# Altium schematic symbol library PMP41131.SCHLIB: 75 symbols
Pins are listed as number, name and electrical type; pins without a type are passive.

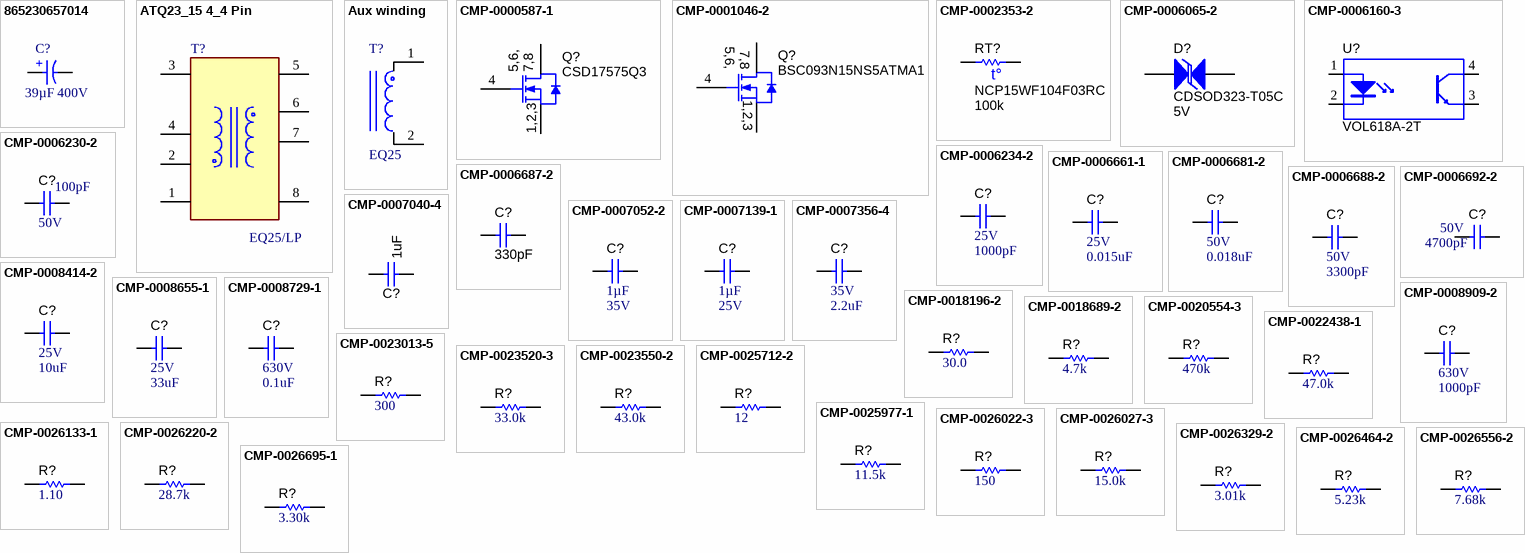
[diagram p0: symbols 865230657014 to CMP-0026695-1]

## 865230657014
designator C?  Rated Voltage (DC): 400V  Cap_F: 39µF
Aluminum Electrolytic Capacitor, Radial, THT, D10 x H20-mm, 39µF, 400V; Manufacturer: Yongming; PartNumber: KCXE2502G470MF; Capacitance Tolerance: +0%/-40%; Case/Size Code: D10 x H20mm; Dissipation Factor: 15%; Endurance: 2000h; Leakage Current: 264uA; Match Code: WCAP-ATG5; Ripple Current: 200mA; Technical Reference: ATJE1602203400DSPA7B0LR; Value: 39uF
footprint 400V27uF_Laydown
pins: 1 P, 2 N

## ATQ23_15 4_4 Pin
designator T?, comment EQ25/LP
ATQ23_15 4_4 Pin
footprint ATQ23.9_13.8_Remove Flywire
pins: 1, 2, 3, 4, 5, 6, 7, 8

## Aux winding
designator T?, comment EQ25
footprint ATQ23.7_15 4+4 Pin
pins: 1, 2

## CMP-0000587-1
designator Q?, comment CSD17575Q3
MOSFET, N-CH, 30 V, 60 A, DQG0008A (VSON-CLIP-8); Manufacturer: Texas Instruments; Alternate Manufacturer: None; U/M: EA; ChType: N; Value: 30V; Value1: 0.003; Rdson45_ohm: 3.2m; Value2: 23 nC; QgTyp_nC: 23; Vgs_V: 20V; IdsMax_A: 60A; AEC Category: Q101; SizeZ_mm: 1.1; SizeX_mm: 3.3; SizeArea_mm2: 10.89; SizeAreaWB_mm2: 18.49
footprint DQG0008A (SMD, 8-Leads, Body 3.3x3.3mm, Pitch 0.65mm)
footprint DQG0008A_NV (SMD, 8-Leads, Body 3.3x3.3mm, Pitch 0.65mm)
pins: 1 S, 2 S, 3 S, 4 G, 5 D, 6 D, 7 D, 8 D, 9 D

## CMP-0001046-2
designator Q?, comment BSC093N15NS5ATMA1
MOSFET, N-CH, 150 V, 87 A, PG-TDSON-8; Alternate Manufacturer: None; Manufacturer: Infineon Technologies; SizeZ_mm: 1.12; ChType: N; Value2: 33 nC; VdsMax_V: 150V; SizeX_mm: 5.99; SizeY_mm: 4.9; Vgs_V: 20V; QgTyp_nC: 33; Value: 150V; SizeArea_mm2: 29.351; AEC Category: Q101; IdsMax_A: 87A; SizeAreaWB_mm2: 55.131; U/M: EA
footprint PG-TDSON-8 (Infineon recommended land pattern)
pins: 1 S, 2 S, 3 S, 4 G, 5 D, 6 D, 7 D, 8 D, 9 D

## CMP-0002353-2
designator RT?, comment NCP15WF104F03RC  value 100k
Thermistor NTC, 100k ohm, 1%, 0402; Manufacturer: MuRata; TaMax_C: 125°C; SizeX_mm: 1; SizeY_mm: 0.5; TaMin_C: -40°C; Power_W: 100mW; SizeZ_mm: 0.6; SizeAreaWB_mm2: 3; U/M: EA
footprint 0402S (Based on C0402S footprint from PADS legacy)
footprint 0402 (0402 from SM-752 data)
footprint 0402L (0402 from SM-752 data)
footprint 0402M (0402 from SM-752 data)
pins: 1, 2

## CMP-0006065-2
designator D?, comment CDSOD323-T05C  value 5V
Diode, TVS, Bi, 5 V, SOD323, 2-Leads, Body 1.9x1.45mm, No Polarity Mark; Manufacturer: Bourns; Ppk: 350W; AEC Category: Q101
footprint SOD-323-Bi (SOD323, 2-Leads, Body 1.9x1.45mm, No Polarity Mark)
pins: 1, 2

## CMP-0006160-3
designator U?, comment VOL618A-2T
Optocoupler, 5 kV, 63-125% CTR, SMT; Manufacturer: Vishay-Semiconductor; Manufacturer: Vishay / Semiconductors; CTR (Max): 125%; SizeAreaWB_mm2: 74.42; CTR (Min): 63%; SizeZ_mm: 2.3; SizeX_mm: 10.2; SizeY_mm: 4.1; SizeArea_mm2: 41.82; Voltage_Isolation_Vrms: 5kV
footprint SOP254P1020X230-4 (VISHAY)
pins: 1 A, 2 K, 3 E, 4 C
1 alternate drawing of the same symbol

## CMP-0006230-2
designator C?, comment VDC_V: 50V  ValueDisplayed: 100pF  (hidden comment: 885012205055)
CAP, CERM, 100 pF, 50 V, +/- 10%, X7R, 0402; Manufacturer: Wurth Elektronik; TaMin_C: -55°C; Polarized: N; SizeAreaWB_mm2: 3; Value1: Unknown; U/M: EA; Value: 100pF; TaMax_C: 125°C; SizeZ_mm: 0.6; SizeX_mm: 1; SizeY_mm: 0.5; Cap_Case: 0402; CompType: Capacitor; AEC Category: Q200
footprint 0402 (0402 from SM-752 data)
footprint 0402S (Based on C0402S footprint from PADS legacy)
footprint 0402L (0402 from SM-752 data)
footprint 0402M (0402 from SM-752 data)
pins: 1, 2

## CMP-0006234-2
designator C?, comment VDC_V: 25V  ValueDisplayed: 1000pF  (hidden comment: C0402C102J3RACTU)
CAP, CERM, 1000 pF, 25 V, +/- 5%, X7R, 0402; Manufacturer: Kemet; TaMin_C: -55°C; Polarized: N; SizeAreaWB_mm2: 3; Value1: Unknown; U/M: EA; Value: 1000pF; TaMax_C: 125°C; SizeZ_mm: 0.6; SizeX_mm: 1; SizeY_mm: 0.5; Cap_Case: 0402; CompType: Capacitor; Cap_F: 1nF; AEC Category: Q200
footprint 0402 (0402 from SM-752 data)
footprint 0402S (Based on C0402S footprint from PADS legacy)
footprint 0402L (0402 from SM-752 data)
footprint 0402M (0402 from SM-752 data)
pins: 1, 2

## CMP-0006661-1
designator C?, comment VDC_V: 25V  ValueDisplayed: 0.015uF  (hidden comment: GRM155R71E153KA61D)
CAP, CERM, 0.015 uF, 25 V, +/- 10%, X7R, 0402; Manufacturer: MuRata; TaMin_C: -55°C; Polarized: N; SizeAreaWB_mm2: 3; Value1: Unknown; U/M: EA; TaMax_C: 125°C; SizeZ_mm: 0.6; SizeX_mm: 1; SizeY_mm: 0.5; Cap_Case: 0402; CompType: Capacitor; Cap_F: 15nF; AEC Category: Q200
footprint 0402 (0402 from SM-752 data)
footprint 0402S (Based on C0402S footprint from PADS legacy)
footprint 0402L (0402 from SM-752 data)
footprint 0402M (0402 from SM-752 data)
pins: 1, 2

## CMP-0006681-2
designator C?, comment VDC_V: 50V  ValueDisplayed: 0.018uF  (hidden comment: GRM155R71H183KA12D)
CAP, CERM, 0.018 uF, 50 V, +/- 10%, X7R, 0402; Manufacturer: MuRata; TaMin_C: -55°C; Polarized: N; SizeAreaWB_mm2: 3; Value1: Unknown; U/M: EA; TaMax_C: 125°C; SizeZ_mm: 0.6; SizeX_mm: 1; SizeY_mm: 0.5; Cap_Case: 0402; CompType: Capacitor; Cap_F: 18nF; AEC Category: Q200
footprint 0402 (0402 from SM-752 data)
footprint 0402S (Based on C0402S footprint from PADS legacy)
footprint 0402L (0402 from SM-752 data)
footprint 0402M (0402 from SM-752 data)
pins: 1, 2

## CMP-0006687-2
designator C?, comment ValueDisplayed: 330pF  (hidden comment: GRM155R71H331KA01D)
CAP, CERM, 330 pF, 50 V, +/- 10%, X7R, 0402; Manufacturer: MuRata; TaMin_C: -55°C; Polarized: N; SizeAreaWB_mm2: 3; Value1: Unknown; U/M: EA; Value: 330pF; TaMax_C: 125°C; SizeZ_mm: 0.6; SizeX_mm: 1; SizeY_mm: 0.5; Cap_Case: 0402; Value2: 50V; CompType: Capacitor; AEC Category: Q200
footprint 0402 (0402 from SM-752 data)
footprint 0402S (Based on C0402S footprint from PADS legacy)
footprint 0402L (0402 from SM-752 data)
footprint 0402M (0402 from SM-752 data)
pins: 1, 2

## CMP-0006688-2
designator C?, comment VDC_V: 50V  ValueDisplayed: 3300pF  (hidden comment: GRM155R71H332KA01D)
CAP, CERM, 3300 pF, 50 V, +/- 10%, X7R, 0402; Manufacturer: MuRata; TaMin_C: -55°C; Polarized: N; SizeAreaWB_mm2: 3; Value1: Unknown; U/M: EA; Value: 3300pF; TaMax_C: 125°C; SizeZ_mm: 0.6; SizeX_mm: 1; SizeY_mm: 0.5; Cap_Case: 0402; CompType: Capacitor; Cap_F: 3.3nF; AEC Category: Q200
footprint 0402 (0402 from SM-752 data)
footprint 0402S (Based on C0402S footprint from PADS legacy)
footprint 0402L (0402 from SM-752 data)
footprint 0402M (0402 from SM-752 data)
pins: 1, 2

## CMP-0006692-2
designator C?, comment VDC_V: 50V  ValueDisplayed: 4700pF  (hidden comment: GRM155R71H472KA01D)
CAP, CERM, 4700 pF, 50 V, +/- 10%, X7R, 0402; Manufacturer: MuRata; TaMin_C: -55°C; Polarized: N; SizeAreaWB_mm2: 3; Value1: Unknown; U/M: EA; Value: 4700pF; TaMax_C: 125°C; SizeZ_mm: 0.6; SizeX_mm: 1; SizeY_mm: 0.5; Cap_Case: 0402; CompType: Capacitor; Cap_F: 4.7nF; AEC Category: Q200
footprint 0402 (0402 from SM-752 data)
footprint 0402S (Based on C0402S footprint from PADS legacy)
footprint 0402L (0402 from SM-752 data)
footprint 0402M (0402 from SM-752 data)
pins: 1, 2

## CMP-0007040-4
designator C?, comment ValueDisplayed: 1uF  (hidden comment: C1608X7R1E105K080AB)
CAP, CERM, 1 µF, 25 V, +/- 10%, X7R, 0603; Manufacturer: TDK; Polarized: N; CompType: Capacitor; Value: 1uF; U/M: EA; Cap_F: 1µF; Value1: Unknown; VDC_V: 25V; TaMin_C: -55°C; TaMax_C: 125°C; Cap_Case: 0603; AEC Category: Q200; SizeArea_mm2: 1.28; SizeAreaWB_mm2: 4.68; SizeX_mm: 1.6; SizeY_mm: 0.8; SizeZ_mm: 1
footprint 0603 (0603 from SM-752 data)
footprint 0603_HV (Ernesto recommended land pattern.  26 mil between pads.)
footprint 0603L (0603 from SM-752 data)
footprint 0603S
footprint 0603M (0603 from SM-752 data)
pins: 1, 2

## CMP-0007052-2
designator C?, comment Cap_F: 1µF  VDC_V: 35V  (hidden comment: C1608X7R1V105K080AC)
CAP, CERM, 1 uF, 35 V, +/- 10%, X7R, 0603; Manufacturer: TDK; TaMin_C: -55°C; Polarized: N; SizeAreaWB_mm2: 4.68; Value1: Unknown; U/M: EA; Value: 1uF; TaMax_C: 125°C; SizeZ_mm: 1; SizeX_mm: 1.6; SizeY_mm: 0.8; Cap_Case: 0603; SizeArea_mm2: 1.28; CompType: Capacitor; AEC Category: Q200
footprint 0603 (0603 from SM-752 data)
footprint 0603_HV (Ernesto recommended land pattern.  26 mil between pads.)
footprint 0603L (0603 from SM-752 data)
footprint 0603S
footprint 0603M (0603 from SM-752 data)
pins: 1, 2

## CMP-0007139-1
designator C?, comment Cap_F: 1µF  VDC_V: 25V  (hidden comment: GCM188R71E105KA64D)
CAP, CERM, 1 uF, 25 V, +/- 10%, X7R, AEC-Q200 Grade 1, 0603; Manufacturer: MuRata; TaMin_C: -55°C; Polarized: N; SizeAreaWB_mm2: 4.68; Value1: Unknown; U/M: EA; Value: 1uF; TaMax_C: 125°C; SizeZ_mm: 1; SizeX_mm: 1.6; SizeY_mm: 0.8; Cap_Case: 0603; SizeArea_mm2: 1.28; CompType: Capacitor; AEC Qualified: Y; AEC Category: Q200
footprint 0603 (0603 from SM-752 data)
footprint 0603_HV (Ernesto recommended land pattern.  26 mil between pads.)
footprint 0603L (0603 from SM-752 data)
footprint 0603S
footprint 0603M (0603 from SM-752 data)
pins: 1, 2

## CMP-0007356-4
designator C?, comment VDC_V: 35V  ValueDisplayed: 2.2uF  (hidden comment: GRM188R6YA225KA12D)
CAP, CERM, 2.2 uF, 35 V, +/- 10%, X5R, 0603; Manufacturer: MuRata; TaMin_C: -55°C; Polarized: N; SizeAreaWB_mm2: 4.68; Value1: Unknown; U/M: EA; Value: 2.2uF; TaMax_C: 85°C; SizeZ_mm: 1; SizeX_mm: 1.6; SizeY_mm: 0.8; Cap_Case: 0603; SizeArea_mm2: 1.28; CompType: Capacitor; Cap_F: 2.2µF; AEC Category: Q200
footprint 0603 (0603 from SM-752 data)
footprint 0603_HV (Ernesto recommended land pattern.  26 mil between pads.)
footprint 0603L (0603 from SM-752 data)
footprint 0603S
footprint 0603M (0603 from SM-752 data)
pins: 1, 2

## CMP-0008414-2
designator C?, comment VDC_V: 25V  ValueDisplayed: 10uF  (hidden comment: TMK212BBJ106KG-T)
CAP, CERM, 10 uF, 25 V, +/- 10%, X5R, 0805; Manufacturer: Taiyo Yuden; TaMin_C: -55°C; Polarized: N; SizeAreaWB_mm2: 6.75; Value1: Unknown; U/M: EA; Value: 10uF; TaMax_C: 85°C; SizeZ_mm: 1.45; SizeX_mm: 2; SizeY_mm: 1.25; Cap_Case: 0805; SizeArea_mm2: 2.5; CompType: Capacitor; Cap_F: 10µF; AEC Category: Q200
footprint 0805_HV (0805 with 30mil clearance between pads)
footprint 0805M (0805 from SM-752 data)
footprint 0805 (0805 from SM-752 data)
footprint 0805L (0805 from SM-752 data)
footprint 0805_HV1 (Custom footprint based on analyzing multiple manufacturer recommendations)
pins: 1, 2

## CMP-0008655-1
designator C?, comment VDC_V: 25V  ValueDisplayed: 33uF  (hidden comment: C3216X5R1E336M160AC)
CAP, CERM, 33 uF, 25 V, +/- 20%, X5R, 1206; Manufacturer: TDK; TaMin_C: -55°C; ESR_ohm: 2.648m; Polarized: N; SizeAreaWB_mm2: 10.92; Value1: 0.002648 ohm; U/M: EA; Value: 33uF; TaMax_C: 85°C; SizeZ_mm: 1.8; SizeX_mm: 3.2; SizeY_mm: 1.6; Cap_Case: 1206_180; SizeArea_mm2: 5.12; CompType: Capacitor; Cap_F: 33µF; IRMS_A: 4.4586A; AEC Category: Q200
footprint 1206_180
footprint 1206_180L (1206_180)
footprint 1206_180M (1206_180)
pins: 1, 2

## CMP-0008729-1
designator C?, comment VDC_V: 630V  ValueDisplayed: 0.1uF  (hidden comment: C3216X7T2W104M160AA)
CAP, CERM, 0.1 uF, 450 V, +/- 20%, X7T, 1206; Manufacturer: TDK; TaMin_C: -55°C; Polarized: N; SizeAreaWB_mm2: 10.92; Value1: Unknown; U/M: EA; Value: 0.1uF; TaMax_C: 125°C; SizeZ_mm: 1.8; SizeX_mm: 3.2; SizeY_mm: 1.6; Cap_Case: 1206; Value2: 450V; SizeArea_mm2: 5.12; CompType: Capacitor; Cap_F: 100nF; AEC Category: Q200
footprint 1206_180
footprint 1206_180L (1206_180)
footprint 1206_180M (1206_180)
pins: 1, 2

## CMP-0008909-2
designator C?, comment VDC_V: 630V  ValueDisplayed: 1000pF  (hidden comment: GRM31BR72J102KW01L)
CAP, CERM, 1000 pF, 630 V, +/- 10%, X7R, 1206; Manufacturer: MuRata; TaMin_C: -55°C; Polarized: N; SizeAreaWB_mm2: 10.92; Value1: Unknown; U/M: EA; Value: 1000pF; TaMax_C: 125°C; SizeZ_mm: 1.35; SizeX_mm: 3.2; SizeY_mm: 1.6; Cap_Case: 1206; SizeArea_mm2: 5.12; CompType: Capacitor; Cap_F: 1nF; AEC Category: Q200
footprint 1206 (1206 from SM-752 data)
footprint 1206L (1206 from SM-752 data)
footprint 1206M (1206 from SM-752 data)
pins: 1, 2

## CMP-0018196-2
designator R?, comment ValueDisplayed: 30.0  (hidden comment: RC1206FR-0730RL)
RES, 30.0, 1%, 0.25 W, 1206; Manufacturer: Yageo America; Power_W: 250mW; TempCo: 100 ppm/C; Value_Code: 30R0; U/M: EA; Value: 30.0; Res_ohm: 30; SizeX_mm: 3.2; SizeY_mm: 1.6; SizeZ_mm: 1.35; Value2: 0.25W; SizeArea_mm2: 5.12; CompType: Resistor; VDC_V: 200V; AEC Category: Q200
footprint 1206 (1206 from SM-752 data)
footprint 1206L (1206 from SM-752 data)
footprint 1206M (1206 from SM-752 data)
pins: 1, 2

## CMP-0018689-2
designator R?, comment ValueDisplayed: 4.7k  (hidden comment: CRCW12064K70JNEA)
RES, 4.7 k, 5%, 0.25 W, 1206; Manufacturer: Vishay-Dale; Manufacturer: Vishay/Dale; Power_W: 250mW; TempCo: 200 ppm/C; Value_Code: 4k70; U/M: EA; Value: 4.7k; EIA_Code: E24; SizeX_mm: 3.2; SizeY_mm: 1.6; SizeZ_mm: 1.35; Value2: 0.25W; SizeArea_mm2: 5.12; CompType: Resistor; VDC_V: 200V; AEC Category: Q200
footprint 1206 (1206 from SM-752 data)
footprint 1206L (1206 from SM-752 data)
footprint 1206M (1206 from SM-752 data)
pins: 1, 2

## CMP-0020554-3
designator R?, comment ValueDisplayed: 470k  (hidden comment: CRCW0805470KJNEA)
RES, 470 k, 5%, 0.125 W, AEC-Q200 Grade 0, 0805; Manufacturer: Vishay-Dale; Manufacturer: Vishay/Dale; Power_W: 125mW; TempCo: 200 ppm/C; Value: 470k; EIA_Code: E24; SizeX_mm: 2; SizeY_mm: 1.25; SizeZ_mm: 1.45; Value2: 0.125W; SizeArea_mm2: 2.5; CompType: Resistor; AEC Qualified: Y; VDC_V: 150V; AEC Category: Q200; AEC Grade: 0
footprint 0805_HV (0805 with 30mil clearance between pads)
footprint 0805M (0805 from SM-752 data)
footprint 0805 (0805 from SM-752 data)
footprint 0805L (0805 from SM-752 data)
footprint 0805_HV1 (Custom footprint based on analyzing multiple manufacturer recommendations)
pins: 1, 2

## CMP-0022438-1
designator R?, comment ValueDisplayed: 47.0k  (hidden comment: CRCW060347K0FKEA)
RES, 47.0 k, 1%, 0.1 W, AEC-Q200 Grade 0, 0603; Manufacturer: Vishay-Dale; Manufacturer: Vishay/Dale; Power_W: 100mW; TempCo: 100 ppm/C; Value_Code: 47k0; U/M: EA; Value: 47.0k; Res_ohm: 47k; SizeX_mm: 1.6; SizeY_mm: 0.8; SizeZ_mm: 1; Value2: 0.1W; SizeArea_mm2: 1.28; CompType: Resistor; AEC Qualified: Y; VDC_V: 75V; AEC Grade: 0; AEC Category: Q200
footprint 0603 (0603 from SM-752 data)
footprint 0603_HV (Ernesto recommended land pattern.  26 mil between pads.)
footprint 0603L (0603 from SM-752 data)
footprint 0603S
footprint 0603M (0603 from SM-752 data)
pins: 1, 2

## CMP-0023013-5
designator R?, comment ValueDisplayed: 300  (hidden comment: RC0603FR-07300RL)
RES, 300, 1%, 0.1 W, 0603; Manufacturer: Yageo; Power_W: 100mW; TempCo: 100 ppm/C; Value_Code: 300R; Value: 300; SizeX_mm: 1.6; SizeY_mm: 0.8; SizeZ_mm: 1; Value2: 0.1W; SizeArea_mm2: 1.28; CompType: Resistor; AEC Qualified: N; VDC_V: 75V; AEC Category: Q200; SizeAreaWB_mm2: 4.68
footprint 0603 (0603 from SM-752 data)
footprint 0603_HV (Ernesto recommended land pattern.  26 mil between pads.)
footprint 0603L (0603 from SM-752 data)
footprint 0603S
footprint 0603M (0603 from SM-752 data)
pins: 1, 2

## CMP-0023520-3
designator R?, comment ValueDisplayed: 33.0k  (hidden comment: RG1608P-333-B-T5)
RES, 33.0 k, 0.1%, 0.1 W, 0603; Manufacturer: Susumu Co Ltd; Power_W: 100mW; TempCo: 25 ppm/C; Value_Code: 33k0; U/M: EA; Value: 33.0k; Res_ohm: 33k; SizeX_mm: 1.6; SizeY_mm: 0.8; SizeZ_mm: 1; Value2: 0.1W; SizeArea_mm2: 1.28; CompType: Resistor; VDC_V: 75V; AEC Category: Q200
footprint 0603 (0603 from SM-752 data)
footprint 0603_HV (Ernesto recommended land pattern.  26 mil between pads.)
footprint 0603L (0603 from SM-752 data)
footprint 0603S
footprint 0603M (0603 from SM-752 data)
pins: 1, 2

## CMP-0023550-2
designator R?, comment ValueDisplayed: 43.0k  (hidden comment: RG1608P-433-B-T5)
RES, 43.0 k, 0.1%, 0.1 W, 0603; Manufacturer: Susumu Co Ltd; Power_W: 100mW; TempCo: 25 ppm/C; Value_Code: 43k0; U/M: EA; Value: 43.0k; Res_ohm: 43k; SizeX_mm: 1.6; SizeY_mm: 0.8; SizeZ_mm: 1; Value2: 0.1W; SizeArea_mm2: 1.28; CompType: Resistor; VDC_V: 75V; AEC Category: Q200
footprint 0603 (0603 from SM-752 data)
footprint 0603_HV (Ernesto recommended land pattern.  26 mil between pads.)
footprint 0603L (0603 from SM-752 data)
footprint 0603S
footprint 0603M (0603 from SM-752 data)
pins: 1, 2

## CMP-0025712-2
designator R?, comment ValueDisplayed: 12  (hidden comment: CRCW060312R0JNEA)
RES, 12, 5%, 0.1 W, 0603; Manufacturer: Vishay-Dale; Power_W: 100mW; TempCo: 200 ppm/C; Value_Code: 12R0; U/M: EA; Value: 12; EIA_Code: E24; SizeX_mm: 1.6; SizeY_mm: 0.8; SizeZ_mm: 1; Value2: 0.1W; SizeArea_mm2: 1.28; CompType: Resistor; VDC_V: 75V; AEC Category: Q200
footprint 0603 (0603 from SM-752 data)
footprint 0603_HV (Ernesto recommended land pattern.  26 mil between pads.)
footprint 0603L (0603 from SM-752 data)
footprint 0603S
footprint 0603M (0603 from SM-752 data)
pins: 1, 2

## CMP-0025977-1
designator R?, comment ValueDisplayed: 11.5k  (hidden comment: CRCW040211K5FKED)
RES, 11.5 k, 1%, 0.063 W, 0402; Manufacturer: Vishay-Dale; Manufacturer: Vishay / Dale; Power_W: 63mW; TempCo: 100 ppm/C; Value_Code: 11k5; U/M: EA; Value: 11.5k; EIA_Code: E96; SizeX_mm: 1; SizeY_mm: 0.5; SizeZ_mm: 0.6; Value2: 0.063W; CompType: Resistor; VDC_V: 50V; AEC Category: Q200
footprint 0402 (0402 from SM-752 data)
footprint 0402S (Based on C0402S footprint from PADS legacy)
footprint 0402L (0402 from SM-752 data)
footprint 0402M (0402 from SM-752 data)
pins: 1, 2

## CMP-0026022-3
designator R?, comment ValueDisplayed: 150  (hidden comment: CRCW0402150RFKED)
RES, 150, 1%, 0.063 W, AEC-Q200 Grade 0, 0402; Manufacturer: Vishay-Dale; Manufacturer: Vishay / Dale; Power_W: 63mW; TempCo: 100 ppm/C; Value_Code: 150R; Value: 150; EIA_Code: E96; SizeX_mm: 1; SizeY_mm: 0.5; SizeZ_mm: 0.6; Value2: 0.063W; CompType: Resistor; AEC Qualified: Y; VDC_V: 50V; AEC Category: Q200; AEC Grade: 0
footprint 0402 (0402 from SM-752 data)
footprint 0402S (Based on C0402S footprint from PADS legacy)
footprint 0402L (0402 from SM-752 data)
footprint 0402M (0402 from SM-752 data)
pins: 1, 2

## CMP-0026027-3
designator R?, comment ValueDisplayed: 15.0k  (hidden comment: CRCW040215K0FKED)
RES, 15.0 k, 1%, 0.063 W, AEC-Q200 Grade 0, 0402; Manufacturer: Vishay-Dale; Manufacturer: Vishay / Dale; Power_W: 63mW; TempCo: 100 ppm/C; Value_Code: 15k0; Value: 15.0k; EIA_Code: E96; Res_ohm: 15k; SizeX_mm: 1; SizeY_mm: 0.5; SizeZ_mm: 0.6; Value2: 0.063W; CompType: Resistor; AEC Qualified: Y; VDC_V: 50V; AEC Category: Q200; AEC Grade: 0
footprint 0402 (0402 from SM-752 data)
footprint 0402S (Based on C0402S footprint from PADS legacy)
footprint 0402L (0402 from SM-752 data)
footprint 0402M (0402 from SM-752 data)
pins: 1, 2

## CMP-0026133-1
designator R?, comment ValueDisplayed: 1.10  (hidden comment: CRCW04021R10FKED)
RES, 1.10, 1%, 0.063 W, 0402; Manufacturer: Vishay-Dale; Power_W: 63mW; TempCo: 100 ppm/C; Value_Code: 1R10; U/M: EA; Value: 1.10; EIA_Code: E96; Res_ohm: 1.1; SizeX_mm: 1; SizeY_mm: 0.5; SizeZ_mm: 0.6; Value2: 0.063W; CompType: Resistor; VDC_V: 50V; AEC Category: Q200
footprint 0402 (0402 from SM-752 data)
footprint 0402S (Based on C0402S footprint from PADS legacy)
footprint 0402L (0402 from SM-752 data)
footprint 0402M (0402 from SM-752 data)
pins: 1, 2

## CMP-0026220-2
designator R?, comment ValueDisplayed: 28.7k  (hidden comment: CRCW040228K7FKED)
RES, 28.7 k, 1%, 0.063 W, AEC-Q200 Grade 0, 0402; Manufacturer: Vishay-Dale; Power_W: 63mW; TempCo: 100 ppm/C; Value_Code: 28k7; Value: 28.7k; EIA_Code: E96; SizeX_mm: 1; SizeY_mm: 0.5; SizeZ_mm: 0.6; Value2: 0.063W; CompType: Resistor; AEC Qualified: Y; VDC_V: 50V; AEC Category: Q200; AEC Grade: 0
footprint 0402 (0402 from SM-752 data)
footprint 0402S (Based on C0402S footprint from PADS legacy)
footprint 0402L (0402 from SM-752 data)
footprint 0402M (0402 from SM-752 data)
pins: 1, 2

## CMP-0026329-2
designator R?, comment ValueDisplayed: 3.01k  (hidden comment: CRCW04023K01FKED)
RES, 3.01 k, 1%, 0.063 W, AEC-Q200 Grade 0, 0402; Manufacturer: Vishay-Dale; Power_W: 63mW; TempCo: 100 ppm/C; Value_Code: 3k01; Value: 3.01k; EIA_Code: E96; SizeX_mm: 1; SizeY_mm: 0.5; SizeZ_mm: 0.6; Value2: 0.063W; CompType: Resistor; AEC Qualified: Y; VDC_V: 50V; AEC Category: Q200; AEC Grade: 0
footprint 0402 (0402 from SM-752 data)
footprint 0402S (Based on C0402S footprint from PADS legacy)
footprint 0402L (0402 from SM-752 data)
footprint 0402M (0402 from SM-752 data)
pins: 1, 2

## CMP-0026464-2
designator R?, comment ValueDisplayed: 5.23k  (hidden comment: CRCW04025K23FKED)
RES, 5.23 k, 1%, 0.063 W, AEC-Q200 Grade 0, 0402; Manufacturer: Vishay-Dale; Power_W: 63mW; TempCo: 100 ppm/C; Value_Code: 5k23; Value: 5.23k; EIA_Code: E96; SizeX_mm: 1; SizeY_mm: 0.5; SizeZ_mm: 0.6; Value2: 0.063W; CompType: Resistor; AEC Qualified: Y; VDC_V: 50V; AEC Category: Q200; AEC Grade: 0
footprint 0402 (0402 from SM-752 data)
footprint 0402S (Based on C0402S footprint from PADS legacy)
footprint 0402L (0402 from SM-752 data)
footprint 0402M (0402 from SM-752 data)
pins: 1, 2

## CMP-0026556-2
designator R?, comment ValueDisplayed: 7.68k  (hidden comment: CRCW04027K68FKED)
RES, 7.68 k, 1%, 0.063 W, AEC-Q200 Grade 0, 0402; Manufacturer: Vishay-Dale; Power_W: 63mW; TempCo: 100 ppm/C; Value_Code: 7k68; Value: 7.68k; EIA_Code: E96; SizeX_mm: 1; SizeY_mm: 0.5; SizeZ_mm: 0.6; Value2: 0.063W; CompType: Resistor; AEC Qualified: Y; VDC_V: 50V; AEC Category: Q200; AEC Grade: 0
footprint 0402 (0402 from SM-752 data)
footprint 0402S (Based on C0402S footprint from PADS legacy)
footprint 0402L (0402 from SM-752 data)
footprint 0402M (0402 from SM-752 data)
pins: 1, 2

## CMP-0026695-1
designator R?, comment ValueDisplayed: 3.30k  (hidden comment: ERJ-2RKF3301X)
RES, 3.30 k, 1%, 0.1 W, AEC-Q200 Grade 0, 0402; Manufacturer: Panasonic; Power_W: 100mW; TempCo: 100 ppm/C; Value_Code: 3k30; U/M: EA; Value: 3.30k; Res_ohm: 3.3k; SizeX_mm: 1; SizeY_mm: 0.5; SizeZ_mm: 0.6; Value2: 0.1W; CompType: Resistor; AEC Qualified: Y; VDC_V: 50V; AEC Grade: 0; AEC Category: Q200
footprint 0402 (0402 from SM-752 data)
footprint 0402S (Based on C0402S footprint from PADS legacy)
footprint 0402L (0402 from SM-752 data)
footprint 0402M (0402 from SM-752 data)
pins: 1, 2

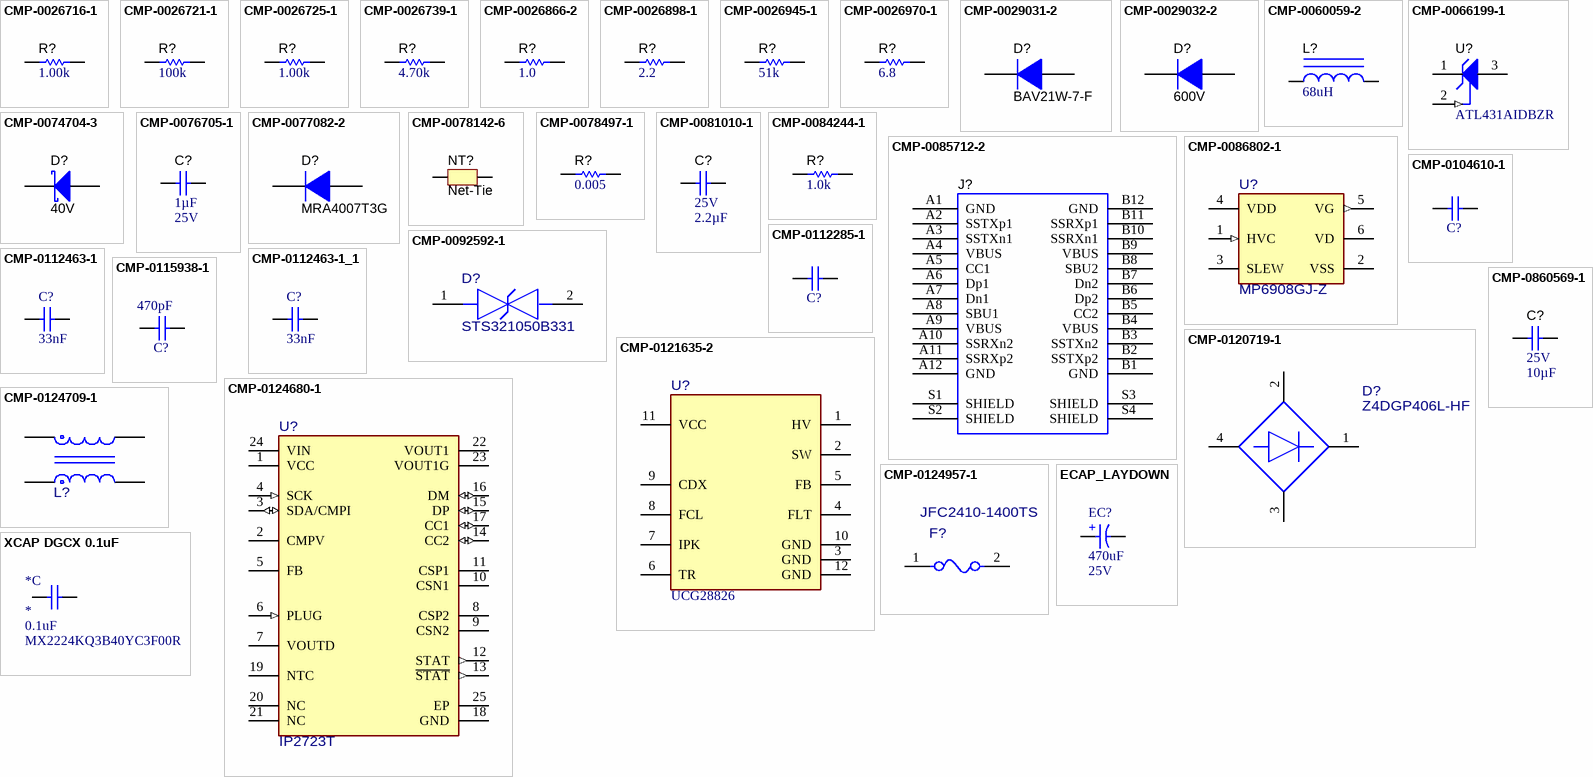
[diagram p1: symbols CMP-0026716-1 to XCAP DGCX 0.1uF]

## CMP-0026716-1
designator R?, comment ValueDisplayed: 1.00k  (hidden comment: MCR01MZPF1001)
RES, 1.00 k, 1%, 0.063 W, 0402; Manufacturer: Rohm; Power_W: 63mW; TempCo: 100 ppm/C; Value_Code: 1k00; U/M: EA; Value: 1.00k; EIA_Code: E96; Res_ohm: 1k; SizeX_mm: 1; SizeY_mm: 0.5; SizeZ_mm: 0.6; Value2: 0.063W; CompType: Resistor; AEC Qualified: N; VDC_V: 50V; AEC Category: Q200
footprint 0402 (0402 from SM-752 data)
footprint 0402S (Based on C0402S footprint from PADS legacy)
footprint 0402L (0402 from SM-752 data)
footprint 0402M (0402 from SM-752 data)
pins: 1, 2

## CMP-0026721-1
designator R?, comment ValueDisplayed: 100k  (hidden comment: RC0402FR-07100KL)
RES, 100 k, 1%, 0.0625 W, 0402; Manufacturer: Yageo America; Power_W: 62.5mW; TempCo: 100 ppm/C; U/M: EA; Value: 100k; EIA_Code: E96; SizeX_mm: 1; SizeY_mm: 0.5; SizeZ_mm: 0.6; CompType: Resistor; AEC Qualified: N; VDC_V: 50V; AEC Category: Q200
footprint 0402 (0402 from SM-752 data)
footprint 0402S (Based on C0402S footprint from PADS legacy)
footprint 0402L (0402 from SM-752 data)
footprint 0402M (0402 from SM-752 data)
pins: 1, 2

## CMP-0026725-1
designator R?, comment ValueDisplayed: 1.00k  (hidden comment: RC0402FR-071KL)
RES, 1.00 k, 1%, 0.0625 W, 0402; Manufacturer: Yageo America; Power_W: 62.5mW; TempCo: 100 ppm/C; Value_Code: 1k00; U/M: EA; Value: 1.00k; EIA_Code: E96; Res_ohm: 1k; SizeX_mm: 1; SizeY_mm: 0.5; SizeZ_mm: 0.6; CompType: Resistor; AEC Qualified: N; VDC_V: 50V; AEC Category: Q200
footprint 0402 (0402 from SM-752 data)
footprint 0402S (Based on C0402S footprint from PADS legacy)
footprint 0402L (0402 from SM-752 data)
footprint 0402M (0402 from SM-752 data)
pins: 1, 2

## CMP-0026739-1
designator R?, comment ValueDisplayed: 4.70k  (hidden comment: RC0402FR-074K7L)
RES, 4.70 k, 1%, 0.0625 W, 0402; Manufacturer: Yageo America; Power_W: 62.5mW; TempCo: 100 ppm/C; Value_Code: 4k70; U/M: EA; Value: 4.70k; Res_ohm: 4.7k; SizeX_mm: 1; SizeY_mm: 0.5; SizeZ_mm: 0.6; CompType: Resistor; AEC Qualified: N; VDC_V: 50V; AEC Category: Q200
footprint 0402 (0402 from SM-752 data)
footprint 0402S (Based on C0402S footprint from PADS legacy)
footprint 0402L (0402 from SM-752 data)
footprint 0402M (0402 from SM-752 data)
pins: 1, 2

## CMP-0026866-2
designator R?, comment ValueDisplayed: 1.0  (hidden comment: CRCW04021R00JNED)
RES, 1.0, 5%, 0.063 W, 0402; Manufacturer: Vishay-Dale; Manufacturer: Vishay / Dale; Power_W: 63mW; TempCo: 200 ppm/C; Value_Code: 1R00; U/M: EA; Value: 1.0; EIA_Code: E24; Res_ohm: 1; SizeY_mm: 0.5; SizeZ_mm: 0.6; Value2: 0.063W; CompType: Resistor; VDC_V: 50V; AEC Category: Q200
footprint 0402 (0402 from SM-752 data)
footprint 0402S (Based on C0402S footprint from PADS legacy)
footprint 0402L (0402 from SM-752 data)
footprint 0402M (0402 from SM-752 data)
pins: 1, 2

## CMP-0026898-1
designator R?, comment ValueDisplayed: 2.2  (hidden comment: CRCW04022R20JNED)
RES, 2.2, 5%, 0.063 W, 0402; Manufacturer: Vishay-Dale; Manufacturer: Vishay / Dale; Power_W: 63mW; TempCo: 200 ppm/C; Value_Code: 2R20; U/M: EA; Value: 2.2; EIA_Code: E24; SizeX_mm: 1; SizeY_mm: 0.5; SizeZ_mm: 0.6; Value2: 0.063W; CompType: Resistor; VDC_V: 50V; AEC Category: Q200
footprint 0402 (0402 from SM-752 data)
footprint 0402S (Based on C0402S footprint from PADS legacy)
footprint 0402L (0402 from SM-752 data)
footprint 0402M (0402 from SM-752 data)
pins: 1, 2

## CMP-0026945-1
designator R?, comment ValueDisplayed: 51k  (hidden comment: CRCW040251K0JNED)
RES, 51 k, 5%, 0.063 W, 0402; Manufacturer: Vishay-Dale; Manufacturer: Vishay / Dale; Power_W: 63mW; TempCo: 200 ppm/C; Value_Code: 51k0; U/M: EA; Value: 51k; EIA_Code: E24; SizeX_mm: 1; SizeY_mm: 0.5; SizeZ_mm: 0.6; Value2: 0.063W; CompType: Resistor; VDC_V: 50V; AEC Category: Q200
footprint 0402 (0402 from SM-752 data)
footprint 0402S (Based on C0402S footprint from PADS legacy)
footprint 0402L (0402 from SM-752 data)
footprint 0402M (0402 from SM-752 data)
pins: 1, 2

## CMP-0026970-1
designator R?, comment ValueDisplayed: 6.8  (hidden comment: CRCW04026R80JNED)
RES, 6.8, 5%, 0.063 W, 0402; Manufacturer: Vishay-Dale; Manufacturer: Vishay / Dale; Power_W: 63mW; TempCo: 200 ppm/C; Value_Code: 6R80; U/M: EA; Value: 6.8; EIA_Code: E24; SizeX_mm: 1; SizeY_mm: 0.5; SizeZ_mm: 0.6; Value2: 0.063W; CompType: Resistor; VDC_V: 50V; AEC Category: Q200
footprint 0402 (0402 from SM-752 data)
footprint 0402S (Based on C0402S footprint from PADS legacy)
footprint 0402L (0402 from SM-752 data)
footprint 0402M (0402 from SM-752 data)
pins: 1, 2

## CMP-0029031-2
designator D?, comment BAV21W-7-F
Diode, Switching, 200 V, 0.2 A, SOD-123; Manufacturer: Diodes Inc.; Manufacturer: Diodes; Green_REACh: Passed; SizeArea_mm2: 6.545; TJmax_C: 150°C; Value2: 1.25V; Io_A: 200mA; SizeAreaWB_mm2: 13.095; SizeY_mm: 1.7; Value: 200V; Green_Lifecycle: Active; SizeX_mm: 3.85; SizeZ_mm: 1.35; AEC Category: Q101; Value1: 0.2A
footprint SOD-123 (On Semi recommended land pattern)
pins: 1 K, 2 A

## CMP-0029032-2
designator D?, comment value 600V  (hidden comment: ES1JFL)
Diode, Switching, 600 V, 1 A, SOD-123; Manufacturer: ON Semiconductor; Manufacturer Part Number: MMSD4148T1G; SizeY_mm: 1.7; Io_A: 1A; SizeAreaWB_mm2: 13.095; SizeArea_mm2: 6.545; Vf_V: 1V; TJmax_C: 150°C; SizeX_mm: 3.85; SizeZ_mm: 1.35; Green_Lifecycle: Active; Green_REACh: Passed
footprint SOD-123 (On Semi recommended land pattern)
pins: 1 K, 2 A

## CMP-0060059-2
designator L?, comment ValueDisplayed: 68uH  (hidden comment: MNR-6045-680MTS)
Inductor, Wirewound, Ferrite, 68 uH, 0.9 A, 0.33 ohm, SMD; Manufacturer: Mag Layers; Isat: 1A @ 30% inductance drop; Irms: 0.9A @ 40C rise; Green_Lifecycle: Not Set; SizeAreaWB_mm2: 64; DCR_ohm: 0.33; Green_REACh: Incomplete; Value: 68uH; Imax_A: 900mA; SizeZ_mm: 4.5; SizeX_mm: 6; Value2: 0.9A; SizeArea_mm2: 36; Ind_H: 68µH; AEC Category: Q200
footprint MNR-6045 (Mag.Layers P/N: MNR-6045-220MTS_Series)
pins: 1, 2

## CMP-0066199-1
designator U?, comment ATL431AIDBZR
2.5V Low Iq Adjustable Precision Shunt Regulator, DBZ0003A (SOT-23-3); Alternate Manufacturer: Texas Instruments; SizeAreaWB_mm2: 14.0; U/M: EA; SizeZ_mm: 1.12; SizeX_mm: 2.5; SizeY_mm: 3.0; SizeArea_mm2: 7.5; CompType: IC
footprint DBZ0003A_N (SOT23, 3-Leads, Body 2.9x1.3mm, Pitch 0.95mm, Lead Span 2.4mm, IPC Medium Density)
footprint DBZ0003A_L (SOT23, 3-Leads, Body 2.9x1.3mm, Pitch 0.95mm, Lead Span 2.4mm, IPC High Density)
footprint DBZ0003A_M (SOT23, 3-Leads, Body 2.9x1.3mm, Pitch 0.95mm, Lead Span 2.4mm, IPC Low Density)
pins: 1 CATHODE, 2 REF (in), 3 ANODE

## CMP-0074704-3
designator D?, comment value 40V  (hidden comment: RB521SM-40T2R)
Diode, Schottky, 40 V, 0.2 A, SOD-523; Manufacturer: Rohm; SizeAreaWB_mm2: 5.13; SizeZ_mm: 0.65; AEC Category: Q101; AEC Qualified: N; Vf_V: 540mV; Io_A: 200mA; Value2: 0.54V; SizeArea_mm2: 1.53; TJmax_C: 150°C; Value1: 0.2A; SizeX_mm: 1.7; SizeY_mm: 0.9
footprint SOD-523 (NXP Semiconductor recommended land pattern, nominal STEP model)
pins: 1 K, 2 A

## CMP-0076705-1
designator C?, comment Cap_F: 1µF  VDC_V: 25V  (hidden comment: CGA3E1X7R1E105K080AC)
CAP, CERM, 1 µF, 25 V,+/- 10%, X7R, AEC-Q200 Grade 1, 0603; Manufacturer: TDK; SizeAreaWB_mm2: 4.68; SizeArea_mm2: 1.28; AEC Qualified: Y; AEC Category: Q200; Value: 1uF; TaMax_C: 125°C; SizeZ_mm: 1.0; AEC Grade: 1; Polarized: N; TaMin_C: -55°C; SizeY_mm: 0.8; U/M: EA; CompType: Capacitor; SizeX_mm: 1.6; Cap_Case: 1.6x0.8x0.8mm
footprint 0603S
footprint 0603_HV (Ernesto recommended land pattern.  26 mil between pads.)
footprint 0603L (0603 from SM-752 data)
footprint 0603M (0603 from SM-752 data)
footprint 0603 (0603 from SM-752 data)
pins: 1, 2

## CMP-0077082-2
designator D?, comment MRA4007T3G
Diode, Standard Recovery Rectifier, 1000 V, 1 A, AEC-Q101, SMA; Manufacturer: ON Semiconductor; Value2: 1.1V; TJmax_C: 175°C; SizeX_mm: 5.59; Green_Lifecycle: Active; Value1: 1A; Green_REACh: Passed; AEC Qualified: Y; AEC Category: Q101; SizeArea_mm2: 16.3228; SizeY_mm: 2.92; SizeAreaWB_mm2: 37.3428; Value: 1000V; RJC_CperW: 16.2; SizeZ_mm: 2.87; Vr_V: 1kV
footprint SMA (Molded Diode, 2-Leads, Body 4.3x2.6mm, IPC Medium Density, based on OnSemi component dimensions and land pattern)
pins: 1 K, 2 A

## CMP-0078142-6
designator NT?, comment Net-Tie  (net tie, no BOM)
Single point connection between nets.
footprint Net-Tie_0805_HV_NoOverlay (0805_HV pads tied by 10mil copper trace which can be cut.  An 0805 part can be placed on pads.)
footprint Net-Tie_10milWide_30milLong (10mil net tie, no solder mask opening, no solder paste)
footprint NetTie_0402 (Net Tie 0402 size)
footprint Net-Tie_50milWide_30milLong (50mil net tie, no solder mask opening, no solder paste)
footprint Net-Tie_20milWide_60milLong (20mil net tie, no solder mask opening, no solder paste)
footprint Net-Tie_6mil (10mil net tie, no solder mask opening, no solder paste)
footprint NetTie_1206_NoOverlay (1206 pads tied by 10mil copper trace which can be cut.  Part can be placed on pads.)
footprint Net-Tie_0805_HV (0805_HV pads tied by 10mil copper trace which can be cut.  An 0805 part can be placed on pads.)
footprint NetTie_1206 (1206 pads tied by 10mil copper trace which can be cut.  Part can be placed on pads.)
footprint Net-Tie_5milWide_60milLong (5mil net tie, no solder mask opening, no solder paste)
footprint NetTie_0603 (Net Tie 0603 size)
footprint Net-Tie_4x6mil
footprint Net-Tie_6x8mil
footprint Net-Tie_4milsWide_10milsLong (Net-Tie 4 mils wide by 10 mils long)
footprint Net-Tie6milsWide_20milsLong (6 mils wide by 20 mils long)
footprint Net-Tie7milsWide_20milsLong (7 mils wide by 20 mils long)
footprint Net-Tie_10mil (10mil net tie, no solder mask opening, no solder paste)
pins: 1, 2

## CMP-0078497-1
designator R?, comment ValueDisplayed: 0.005  (hidden comment: CSR1206-0R005F1)
RES, 0.005, 1%, 1 W, 1206; Manufacturer: Riedon; Power_W: 1W; TempCo: 50 ppm/C; Value_Code: 5L000; Value: 0.005; EIA_Code: E96; Res_ohm: 5m; SizeX_mm: 3.2; SizeY_mm: 1.6; SizeZ_mm: 1.35; SizeArea_mm2: 5.12; CompType: Resistor; AEC Qualified: N; AEC Category: Q200
footprint 1206 (1206 from SM-752 data)
footprint 1206M (1206 from SM-752 data)
footprint 1206L (1206 from SM-752 data)
pins: 1, 2

## CMP-0081010-1
designator C?, comment VDC_V: 25V  ValueDisplayed: 2.2µF  (hidden comment: GRM155R61E225ME15D)
CAP, CERM, 2.2 µF, 25 V,+/- 20%, X5R, 0402; Manufacturer: MuRata; SizeAreaWB_mm2: 3; SizeArea_mm2: 0.5; AEC Qualified: N; AEC Category: Q200; Value: 2.2uF; TaMax_C: 85°C; SizeZ_mm: 0.6; TaMin_C: -55°C; U/M: EA; CompType: Capacitor; SizeX_mm: 1; Cap_Case: 0402
footprint 0402 (0402 from SM-752 data)
footprint 0402M (0402 from SM-752 data)
footprint 0402L (0402 from SM-752 data)
footprint 0402S (Based on C0402S footprint from PADS legacy)
pins: 1, 2

## CMP-0084244-1
designator R?, comment ValueDisplayed: 1.0k  (hidden comment: ESR03EZPJ102)
RES, 1.0 k, 5%, 0.25 W, AEC-Q200 Grade 0, 0603; Manufacturer: Rohm; Power_W: 250mW; TempCo: 200 ppm/C; SizeAreaWB_mm2: 4.68; Value_Code: 1k00; Value: 1.0k; EIA_Code: E24; Res_ohm: 1k; SizeX_mm: 1.6; SizeY_mm: 0.8; SizeZ_mm: 1; Value2: 0.25W; SizeArea_mm2: 1.28; CompType: Resistor; AEC Qualified: Y; AEC Grade: 0; AEC Category: Q200
footprint 0603 (0603 from SM-752 data)
footprint 0603M (0603 from SM-752 data)
footprint 0603L (0603 from SM-752 data)
footprint 0603_HV (Ernesto recommended land pattern.  26 mil between pads.)
footprint 0603S
pins: 1, 2

## CMP-0085712-2
designator J?, comment DX07S024JJ2R1300  (value not drawn)
Receptacle, USB 3.1 Type C, R/A, Gold, SMT; Manufacturer: JAE Electronics; Current_A: 1.25A; Gender: Female; Voltage_V: 20V; Pitch_mm: 0.5; Row_Count: 2
footprint JAE_DX07S024JJ2R1300 (Receptacle, USB 3.1 Type C, R/A, SMT)
pins: A1 GND, A2 SSTXp1, A3 SSTXn1, A4 VBUS, A5 CC1, A6 Dp1, A7 Dn1, A8 SBU1, A9 VBUS, A10 SSRXn2, A11 SSRXp2, A12 GND, B1 GND, B2 SSTXp2, B3 SSTXn2, B4 VBUS, B5 CC2, B6 Dp2, B7 Dn2, B8 SBU2, B9 VBUS, B10 SSRXn1, B11 SSRXp1, B12 GND, S1 SHIELD, S2 SHIELD, S3 SHIELD, S4 SHIELD

## CMP-0086802-1
designator U?, comment MP6908GJ-Z
FAST TURN-OFF INTELLIGENT RECTIF; Manufacturer: Monolithic Power Systems; SizeZ_mm: 1mm; Symbol Name: SYM-MP6908GJ-Z
footprint FP-MP6908GJ-Z_TSOT23-6-MFG
footprint FP-MP6908GJ-Z_TSOT23-6-IPC_C
footprint FP-MP6908GJ-Z_TSOT23-6-IPC_B
footprint FP-MP6908GJ-Z_TSOT23-6-IPC_A
pins: 1 HVC (in), 2 VSS (power), 3 SLEW, 4 VDD (power), 5 VG (out), 6 VD (hiz)

## CMP-0092592-1
designator D?, comment STS321050B331
18V Clamp 22A (8/20µs) Ipp Tvs Diode Surface Mount SOD-323; Manufacturer: Eaton; ValueDisplayed: 33pF; Breakdown Voltage: 5.5V; Number Of Channels: 1; SizeZ_mm: 1mm; AEC Qualified: No; Ppk: 400W; VRWM: 5V; TJmax_C: +125°C; Direction: Bidirectional
footprint FP-STS321050B331_SOD-323-MFG
footprint FP-STS321050B331_SOD-323-IPC_C
footprint FP-STS321050B331_SOD-323-IPC_B
footprint FP-STS321050B331_SOD-323-IPC_A
pins: 1, 2

## CMP-0104610-1
designator C?, comment 885012205042  (value not drawn)
WCAP-CSGP Multilayer Ceramic Chip Capacitor, General Purpose, size 0402, X7R, 470pF, 25VDC; Manufacturer: Wurth Elektronik; Manufacturer: Wurth Electronics; Capacitance Tolerance: +/-10%; Case/Size Code: 0402; Dissipation Factor: 3.5%; Insulation Resistance: 10GOhm; Rated Voltage (DC): 25V; Technical Reference: X7R0402471K025DFCT10000
footprint WCAP-CSGP_0402_L1W0.5H0.5 (Ceramic Capacitors, body 1x0.5mm)
pins: 1, 2

## CMP-0112285-1
designator C?, comment 885342207003  (value not drawn)
WCAP-CSMH Multilayer Ceramic Chip Capacitor, Mid and High Voltage, size 0805, X7R Class II, 1nF, 200VDC; Manufacturer: Wurth Elektronik; Manufacturer: Wurth Electronics; Capacitance Tolerance: 10%; Case/Size Code: 0805; Dissipation Factor: 2.5%; Insulation Resistance: 10GOhm; Rated Voltage (DC): 200V; Technical Reference: X7R0805102K200DFCT10000
footprint WCAP-CSMH_0805_L2W1.25H0.8_Reflow (Ceramic Capacitors, body 2x1.25mm)
footprint WCAP-CSMH_0805_L2W1.25H0.8_Wave (Ceramic Capacitors, body 2x1.25mm)
pins: 1, 2

## CMP-0112463-1
designator C?, comment Cap_F: 33nF  (hidden comment: SCC2220X333K252T)
2220 SMD, 33nF, 250VAC, Holley Stone; Manufacturer Part Number: 890324023028; Capacitance Tolerance: +/-10%; Dissipation Factor @100kHz: 2%; Dissipation Factor @10kHz: 0.2%; Dissipation Factor @1kHz: 0.1%; Insulation Resistance: 30000MOhm; Match Code: WCAP-FTX2; Pitch: 10mm; Rate of Voltage Rise: 300V/us; Rated Voltage (AC): 275V; Technical Reference: MX2P010224K275ASPB16000
footprint WCAP-FTX2_L13W8H14 (Film Capacitors, 13x8x14mm)
footprint 2220_280 (Chip Capacitor, Body 5.7x5.0mm, IPC Medium Density)
pins: 1, 2

## CMP-0112463-1_1
designator C?, comment Cap_F: 33nF  (hidden comment: SCC2220X333K252T)
2220 SMD, 33nF, 250VAC; Manufacturer: Holly Stone; Manufacturer Part Number: 890324023028; Capacitance Tolerance: +/-10%; Dissipation Factor @100kHz: 2%; Dissipation Factor @10kHz: 0.2%; Dissipation Factor @1kHz: 0.1%; Insulation Resistance: 30000MOhm; Match Code: WCAP-FTX2; Pitch: 10mm; Rate of Voltage Rise: 300V/us; Rated Voltage (AC): 275V; Technical Reference: MX2P010224K275ASPB16000
footprint WCAP-FTX2_L13W8H14 (Film Capacitors, 13x8x14mm)
footprint 2220_280 (Chip Capacitor, Body 5.7x5.0mm, IPC Medium Density)
pins: 1, 2

## CMP-0115938-1
designator C?, comment Cap_F: 470pF  (hidden comment: 885362210009)
WCAP-CSSA Multilayer Ceramic Chip Safety Capacitor, size 1808, X7R Class II, 470pF, 250VAC; Manufacturer: Wurth Elektronik; Manufacturer: Wurth Electronics; Capacitance Tolerance: +/-10%; Case/Size Code: 1808; Dissipation Factor: 2.5%; Impulse Voltage: 2500VDC; Insulation Resistance: 10GOhm; Rated Voltage (AC): 250V; Safety Class: X2; Technical Reference: X7R1808471KB50IFCT10000
footprint WCAP-CSSA_1808_L4.5W2H1.6 (Ceramic Capacitors, body 4.50x2.00mm)
pins: 1, 2

## CMP-0120719-1
designator D?, comment Z4DGP406L-HF
Bridge Rectifier Single Phase Standard 600 V Surface Mount Z4-D; Manufacturer: Comchip; AEC Qualified: No; SizeZ_mm: 1.45mm; TJmax_C: 175°C; Vf_V: 600V; Cap_F: 45pF; Forward Current: 4A; Max Surge Forward Current: 150A; Peak Reverse Current: 0.08uA
footprint FP-Z4DGP406L-HF_SMT_8MM1_10MM5-MFG
pins: 1 +, 2 1_~, 3 2_~, 4 -

## CMP-0121635-2
designator U?, comment PartNumber: UCG28826  (hidden comment: UCG28682)
Manufacturer: Texas Instruments; SizeZ_mm: 1mm; Standoff Height: 0mm; AEC Category: Q200; CompType: IC
footprint REZ0012A-MFG
pins: 1 HV (power), 2 SW (power), 3 GND (power), 4 FLT, 5 FB, 6 TR, 7 IPK, 8 FCL, 9 CDX, 10 GND (power), 11 VCC (power), 12 GND (power)

## CMP-0124680-1
designator U?, comment IP2723T
Integrate multiple protocols, fast charging protocol IC for USBC port; Manufacturer: Injoinic; PartNumber: IP2723TH; SizeZ_mm: 0.8mm; AEC Qualified: No; Max Supply Voltage: 25V; Min Supply Voltage: 3V; Standoff Height: 0.02mm; TaMax_C: +85°C; TaMin_C: -40°C; TJmax_C: +150°C
footprint FP-IP2723TH_QFN24-IPC_C
footprint FP-IP2723TH_QFN24-IPC_B
footprint FP-IP2723TH_QFN24-IPC_A
pins: 1 VCC (power), 2 CMPV, 3 SDA/CMPI (io), 4 SCK (in), 5 FB, 6 PLUG (in), 7 VOUTD, 8 CSP2, 9 CSN2, 10 CSN1, 11 CSP1, 12 STAT (out), 13 ~{STAT} (out), 14 CC2 (io), 15 DP (io), 16 DM (io), 17 CC1 (io), 18 GND (power), 19 NTC, 20 NC, 21 NC, 22 VOUT1, 23 VOUT1G, 24 VIN (power), 25 EP

## CMP-0124709-1
designator L?, comment MDM-9070F-102  (value not drawn)
Wire Wound Common Mode Choke 1000Ohm @ 100MHz, 4A IDC, 9.0x7.0x4.8mm SMT; Manufacturer: MAG-AGA; DCR_ohm: 13m; SizeZ_mm: 4.8mm; AEC Qualified: No; Impedance At Frequency: 1000Ω @ 100MHz
footprint FP-MDM-9070F-102_SMT_CMC_9MM0_7MM0-MFG (Recommended Land Pattern)
pins: 1, 2, 3, 4

## CMP-0124957-1
designator F?, comment JFC2410-1400TS
50A SMD Fuse 4A 250V 250V SMD Disposable fuses ROHS; Manufacturer: Shenzhen JDT Fuse; MeltingTyp: 34.4A2Sec; SizeZ_mm: 2.8mm; Fuse Speed: Slow; AEC Qualified: No; Res_ohm: 0.0186Ω
footprint FP-JFC2410-1400TS_SMT_FUSE_6MM1_2MM6-MFG (Recommended Land Pattern)
footprint FP-JFC2410-1400TS_SMT_FUSE_6MM1_2MM6-IPC_C
footprint FP-JFC2410-1400TS_SMT_FUSE_6MM1_2MM6-IPC_B
footprint FP-JFC2410-1400TS_SMT_FUSE_6MM1_2MM6-IPC_A
pins: 1, 2

## CMP-0860569-1
designator C?, comment VDC_V: 25V  ValueDisplayed: 10µF  (hidden comment: GRM188R61E106KA73D)
CAP, CERM, 10 µF, 25 V,+/- 10%, X5R, 0603; Manufacturer: MuRata; SizeZ_mm: 1; AEC Category: Q200; AEC Qualified: N; TaMin_C: -55°C; Cap_Case: 0603; SizeY_mm: 0.8; SizeAreaWB_mm2: 4.68; SizeArea_mm2: 1.28; TaMax_C: 85°C; SizeX_mm: 1.6; Value: 10uF; CompType: Capacitor; U/M: EA
footprint 0603 (0603 from SM-752 data)
footprint 0603M (0603 from SM-752 data)
footprint 0603L (0603 from SM-752 data)
footprint 0603_HV (Ernesto recommended land pattern.  26 mil between pads.)
footprint 0603S
pins: 1, 2

## ECAP_LAYDOWN
designator EC?  value 470uF  Voltage: 25V  (hidden comment: ECAP_LAYDOWN)
25V/470uF D5.5*11mm
footprint CE05.5P254L11
pins: 1 P, 2 N

## XCAP DGCX 0.1uF
designator *C  value 0.1uF  PartNumber: MX2224KQ3B40YC3F00R
footprint XCAP DGXC 0.1UF
pins: 1, 2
